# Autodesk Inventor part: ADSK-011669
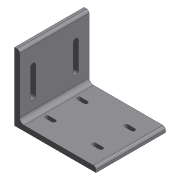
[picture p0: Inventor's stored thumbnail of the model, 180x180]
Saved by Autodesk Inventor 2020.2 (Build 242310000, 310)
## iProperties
Created: 2000-02
Part Number: ADSK-011669
Material: Pearson HRS
Document SubType Name: Modeling
Designer: sspink
Density: 7.83 g/cm^3
Appearance: Métal - Acier
Mass: 2497.25 g
Surface Area: 777.787 cm^2
Volume: 318.934 cm^3
Control State: 0
Checked Out: False
Master: False
Shininess: 0.0
Length Units: 11269
Angle Units: 11279
Time Units: 11290
Mass Units: 11283
Length Display Precision: 3
Angle Display Precision: 2
Compacted: True
Cutlength: 23.25
Material Desc: Material Description goes here
Material_Number: Pearson
Dimensions: 127x130x152,4 mm
Mass: 2,497 kg
VLT_Material: Pearson HRS
Density: 0.0
Volumn: 0.0
Area: 0.0
PropertySet Name: Model Information
Author: sspink
Revision Number: -
Title: ADSK-011669
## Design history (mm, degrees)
node "Element2:1"
node "Extrusion1" dims "d12" = 25.4, "d13" = 0
  sketch "Sketch3"
    geometry: L1 (0, 127)-(130, 127) reference; L2 (30, 39)-(20, 39); L3 (20, 39)-(20, 89); L4 (20, 89)-(30, 89); L5 (30, 89)-(30, 39); L6 (110, 39)-(100, 39); L7 (100, 39)-(100, 89); L8 (100, 89)-(110, 89); L9 (110, 89)-(110, 39); L10 (130, 0)-(130, 127) reference; L11 (25, 89)-(25, 36.767); L12 (105, 89)-(105, 39); L13 (25, 62.883)-(105, 62.883); A1 r 5 centre (25, 39) between (20, 39) and (30, 39); A2 r 5 centre (25, 89) between (30, 89) and (20, 89); A3 r 5 centre (105, 39) between (100, 39) and (110, 39); A4 r 5 centre (105, 89) between (110, 89) and (100, 89); 3 further points
    constraints: 22 end point, 8 point on circle, 5 midpoint, 4 centre point, 4 parallel, 4 tangent, 3 perpendicular, 2 horizontal, 2 vertical, 1 horizontal alignment, 1 point on line, 1 vertical alignment
    dimensions: "d8" = 50 distance of L2.end L3.end; "d9" = 10 distance between parallel lines of L5 L3; "d11" = 38 distance from line of A2.centre L1; "d31" = 50 distance of L6.end L7.end; "d32" = 10 distance between parallel lines of L9 L7; "d34" = 80 distance of L13.start L13.end
node "Extrusion2" dims "d23" = 25.4, "d24" = 0
  sketch "Sketch4"
    geometry: L1 (152.4, 130)-(0, 130) reference; L2 (0, 0)-(0, 130) reference; L3 (0, 0)-(152.4, 0) reference; L4 (152.4, 0)-(152.4, 130) reference; L5 (25.5, 98.5)-(38.2, 98.5); L6 (38.2, 98.5)-(38.2, 91.5); L7 (38.2, 91.5)-(25.5, 91.5); L8 (25.5, 91.5)-(25.5, 98.5); L9 (0, 65)-(152.4, 65); L10 (76.2, 130)-(76.2, 0); L11 (114.2, 38.5)-(126.9, 38.5); L12 (126.9, 38.5)-(126.9, 31.5); L13 (126.9, 31.5)-(114.2, 31.5); L14 (114.2, 31.5)-(114.2, 38.5); L15 (25.5, 38.5)-(38.2, 38.5); L16 (38.2, 38.5)-(38.2, 31.5); L17 (38.2, 31.5)-(25.5, 31.5); L18 (25.5, 31.5)-(25.5, 38.5); L19 (114.2, 98.5)-(126.9, 98.5); L20 (126.9, 98.5)-(126.9, 91.5); L21 (126.9, 91.5)-(114.2, 91.5); L22 (114.2, 91.5)-(114.2, 98.5); A1 r 3.5 centre (38.2, 95) between (38.2, 91.5) and (38.2, 98.5); A2 r 3.5 centre (25.5, 95) between (25.5, 98.5) and (25.5, 91.5); A3 r 3.5 centre (126.9, 35) between (126.9, 31.5) and (126.9, 38.5); A4 r 3.5 centre (114.2, 35) between (114.2, 38.5) and (114.2, 31.5); A5 r 3.5 centre (38.2, 35) between (38.2, 31.5) and (38.2, 38.5); A6 r 3.5 centre (25.5, 35) between (25.5, 38.5) and (25.5, 31.5); A7 r 3.5 centre (126.9, 95) between (126.9, 91.5) and (126.9, 98.5); A8 r 3.5 centre (114.2, 95) between (114.2, 98.5) and (114.2, 91.5); 5 further points
    constraints: 36 end point, 16 point on circle, 9 midpoint, 8 centre point, 8 parallel, 8 tangent, 4 horizontal, 4 perpendicular, 2 horizontal alignment, 2 vertical alignment
    dimensions: "d17" = 12.7 distance of L6.end L7.end; "d18" = 7 distance between parallel lines of L7 L5; "d21" = 30 distance from line of A1.centre L9; "d22" = 38 distance from line of A1.centre L10; "d35" = 12.7 distance of L12.end L13.end; "d36" = 7 distance between parallel lines of L13 L11; "d37" = 12.7 distance of L16.end L17.end; "d38" = 7 distance between parallel lines of L17 L15; "d39" = 12.7 distance of L20.end L21.end; "d40" = 7 distance between parallel lines of L21 L19; "d41" = 38 distance between parallel lines of L10 L22 (= d22); "d42" = 30 distance from line of L9 A6.centre (= d21)
workplane "Arbeitsebene1"
node "Solide1"
node "Corps solides"
node "Corps surfaciques"
sketch "Sketch2"
  geometry: L1 (32.408, 38.758)-(184.808, 38.758); L2 (32.408, 165.758)-(32.408, 38.758); L3 (41.933, 160.995)-(41.933, 56.538); L4 (50.188, 48.283)-(180.045, 48.283); L5 (32.408, 165.758)-(37.17, 165.758); L6 (184.808, 43.52)-(184.808, 38.758); A1 r 4.763 centre (37.17, 160.995) between (41.933, 160.995) and (37.17, 165.758); A2 r 4.763 centre (180.045, 43.52) between (184.808, 43.52) and (180.045, 48.283); A3 r 8.255 centre (50.188, 56.538) between (41.933, 56.538) and (50.188, 48.283); 1 further point
  constraints: 12 end point, 6 point on circle, 6 tangent, 3 centre point, 1 coincident, 1 equal radius, 1 horizontal, 1 perpendicular, 1 other
  dimensions: "d0" = 9.525 distance between parallel lines of L2 L3 (derived); "d6" = 4.7625 radius of A1 (derived); "d7" = 8.255 radius of A3 (derived); "d2" = 127 distance between parallel lines of L1 L5 (derived); "d4" = 152.4 distance between parallel lines of L6 L2 (derived)
